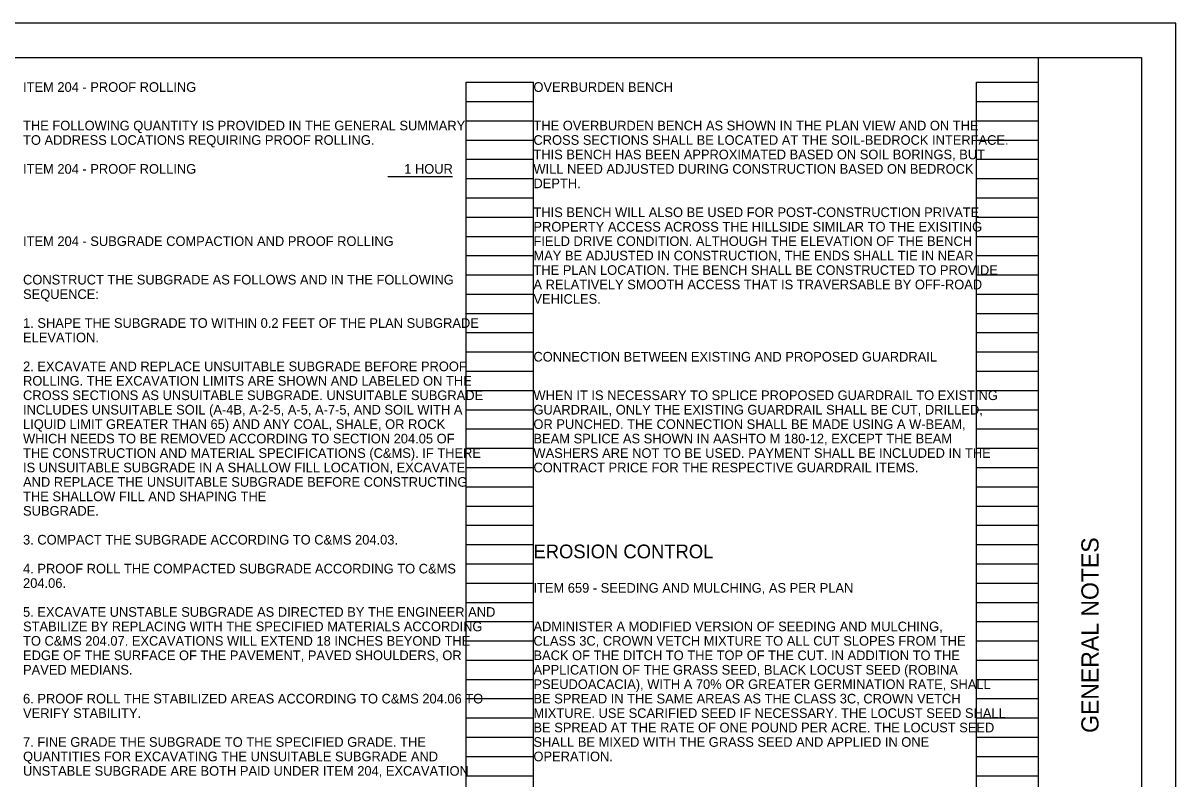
# Model space of a CAD drawing. Extents: x 0 to 34, y 0 to 22.
# Drawn here: x 17.24 to 34, y 11.01 to 22 of the extents above; entities that cross this region are included whole.
import ezdxf

# ---------------------------------------------------------------- set-up
doc = ezdxf.new("R2010")
doc.units = 0
for name, color, linetype in [('SH_Border', 7, 'Continuous'), ('SH_Cut_Line', 7, 'Continuous'), ('SH_Data', 7, 'Continuous'), ('SH_Text', 7, 'Continuous'), ('TX_P_Misc', 7, 'Continuous')]:
    doc.layers.add(name, color=color, linetype=linetype)

msp = doc.modelspace()

# ---------------------------------------------------------------- linework, layer by layer
at = {"layer": 'SH_Border'}
msp.add_line((32, 0.5), (32, 21.5), dxfattribs=at)
msp.add_lwpolyline([(1.5, 21.5), (33.5, 21.5), (33.5, 0.5), (1.5, 0.5)], close=True, dxfattribs=at)
at = {"layer": 'SH_Cut_Line'}
msp.add_lwpolyline([(0, 0), (34, 0), (34, 22), (0, 22)], close=True, dxfattribs=at)
at = {"layer": 'SH_Data'}
for p, q in [((23.68, 0.98), (23.68, 21.14)), ((23.68, 21.14), (24.66, 21.14)), ((24.66, 0.98), (24.66, 21.14)), ((31.1, 0.98), (31.1, 21.14)), ((31.1, 21.14), (32, 21.14)), ((32, 0.98), (32, 21.14)), ((23.68, 20.86), (24.66, 20.86)), ((31.1, 20.86), (32, 20.86)), ((23.68, 20.58), (24.66, 20.58)), ((31.1, 20.58), (32, 20.58)), ((23.68, 20.3), (24.66, 20.3)), ((31.1, 20.3), (32, 20.3)), ((23.68, 20.02), (24.66, 20.02)), ((31.1, 20.02), (32, 20.02)), ((23.68, 19.74), (24.66, 19.74)), ((31.1, 19.74), (32, 19.74)), ((23.68, 19.46), (24.66, 19.46)), ((31.1, 19.46), (32, 19.46)), ((23.68, 19.18), (24.66, 19.18)), ((31.1, 19.18), (32, 19.18)), ((23.68, 18.9), (24.66, 18.9)), ((31.1, 18.9), (32, 18.9)), ((23.68, 18.62), (24.66, 18.62)), ((31.1, 18.62), (32, 18.62)), ((23.68, 18.34), (24.66, 18.34)), ((31.1, 18.34), (32, 18.34)), ((23.68, 18.06), (24.66, 18.06)), ((31.1, 18.06), (32, 18.06)), ((23.68, 17.78), (24.66, 17.78)), ((31.1, 17.78), (32, 17.78)), ((23.68, 17.5), (24.66, 17.5)), ((31.1, 17.5), (32, 17.5)), ((23.68, 17.22), (24.66, 17.22)), ((31.1, 17.22), (32, 17.22)), ((23.68, 16.94), (24.66, 16.94)), ((31.1, 16.94), (32, 16.94)), ((23.68, 16.66), (24.66, 16.66)), ((31.1, 16.66), (32, 16.66)), ((23.68, 16.38), (24.66, 16.38)), ((31.1, 16.38), (32, 16.38)), ((23.68, 16.1), (24.66, 16.1)), ((31.1, 16.1), (32, 16.1)), ((23.68, 15.82), (24.66, 15.82)), ((31.1, 15.82), (32, 15.82)), ((23.68, 15.54), (24.66, 15.54)), ((31.1, 15.54), (32, 15.54)), ((23.68, 15.26), (24.66, 15.26)), ((31.1, 15.26), (32, 15.26)), ((23.68, 14.98), (24.66, 14.98)), ((31.1, 14.98), (32, 14.98)), ((23.68, 14.7), (24.66, 14.7)), ((31.1, 14.7), (32, 14.7)), ((23.68, 14.42), (24.66, 14.42)), ((31.1, 14.42), (32, 14.42)), ((23.68, 14.14), (24.66, 14.14)), ((31.1, 14.14), (32, 14.14)), ((23.68, 13.86), (24.66, 13.86)), ((31.1, 13.86), (32, 13.86)), ((23.68, 13.58), (24.66, 13.58)), ((31.1, 13.58), (32, 13.58)), ((23.68, 13.3), (24.66, 13.3)), ((31.1, 13.3), (32, 13.3)), ((23.68, 13.02), (24.66, 13.02)), ((31.1, 13.02), (32, 13.02)), ((23.68, 12.74), (24.66, 12.74)), ((31.1, 12.74), (32, 12.74)), ((23.68, 12.46), (24.66, 12.46)), ((31.1, 12.46), (32, 12.46)), ((23.68, 12.18), (24.66, 12.18)), ((31.1, 12.18), (32, 12.18)), ((23.68, 11.9), (24.66, 11.9)), ((31.1, 11.9), (32, 11.9)), ((23.68, 11.62), (24.66, 11.62)), ((31.1, 11.62), (32, 11.62)), ((23.68, 11.34), (24.66, 11.34)), ((31.1, 11.34), (32, 11.34)), ((23.68, 11.06), (24.66, 11.06)), ((31.1, 11.06), (32, 11.06))]:
    msp.add_line(p, q, dxfattribs=at)
at = {"layer": 'TX_P_Misc'}
msp.add_line((22.545, 19.771), (23.481, 19.771), dxfattribs=at)

# ---------------------------------------------------------------- texts
at = {"layer": 'SH_Data'}
msp.add_text('GENERAL NOTES', height=0.25, rotation=90, dxfattribs=at).set_placement((32.875, 11.682))
at = {"layer": 'SH_Text'}
for s, height, p in [('ITEM 204 - PROOF ROLLING', 0.14, (17.24, 21)), ('OVERBURDEN BENCH', 0.14, (24.66, 21)), ('THE FOLLOWING QUANTITY IS PROVIDED IN THE GENERAL SUMMARY ', 0.14, (17.24, 20.44)), ('THE OVERBURDEN BENCH AS SHOWN IN THE PLAN VIEW AND ON THE ', 0.14, (24.66, 20.44)), ('TO ADDRESS LOCATIONS REQUIRING PROOF ROLLING.', 0.14, (17.24, 20.23)), ('CROSS SECTIONS SHALL BE LOCATED AT THE SOIL-BEDROCK INTERFACE. ', 0.14, (24.66, 20.23)), ('THIS BENCH HAS BEEN APPROXIMATED BASED ON SOIL BORINGS, BUT ', 0.14, (24.66, 20.02)), ('ITEM 204 - PROOF ROLLING', 0.14, (17.24, 19.81)), ('WILL NEED ADJUSTED DURING CONSTRUCTION BASED ON BEDROCK ', 0.14, (24.66, 19.81)), ('DEPTH.', 0.14, (24.66, 19.6)), ('THIS BENCH WILL ALSO BE USED FOR POST-CONSTRUCTION PRIVATE ', 0.14, (24.66, 19.18)), ('PROPERTY ACCESS ACROSS THE HILLSIDE SIMILAR TO THE EXISITING ', 0.14, (24.66, 18.97)), ('ITEM 204 - SUBGRADE COMPACTION AND PROOF ROLLING', 0.14, (17.24, 18.76)), ('FIELD DRIVE CONDITION. ALTHOUGH THE ELEVATION OF THE BENCH ', 0.14, (24.66, 18.76)), ('MAY BE ADJUSTED IN CONSTRUCTION, THE ENDS SHALL TIE IN NEAR ', 0.14, (24.66, 18.55)), ('THE PLAN LOCATION. THE BENCH SHALL BE CONSTRUCTED TO PROVIDE ', 0.14, (24.66, 18.34)), ('CONSTRUCT THE SUBGRADE AS FOLLOWS AND IN THE FOLLOWING ', 0.14, (17.24, 18.2)), ('A RELATIVELY SMOOTH ACCESS THAT IS TRAVERSABLE BY OFF-ROAD ', 0.14, (24.66, 18.13)), ('SEQUENCE:', 0.14, (17.24, 17.99)), ('VEHICLES.', 0.14, (24.66, 17.92)), ('1. SHAPE THE SUBGRADE TO WITHIN 0.2 FEET OF THE PLAN SUBGRADE ', 0.14, (17.24, 17.57)), ('ELEVATION.', 0.14, (17.24, 17.36)), ('CONNECTION BETWEEN EXISTING AND PROPOSED GUARDRAIL', 0.14, (24.66, 17.08)), ('2. EXCAVATE AND REPLACE UNSUITABLE SUBGRADE BEFORE PROOF ', 0.14, (17.24, 16.94)), ('ROLLING. THE EXCAVATION LIMITS ARE SHOWN AND LABELED ON THE ', 0.14, (17.24, 16.73)), ('CROSS SECTIONS AS UNSUITABLE SUBGRADE. UNSUITABLE SUBGRADE ', 0.14, (17.24, 16.52)), ('WHEN IT IS NECESSARY TO SPLICE PROPOSED GUARDRAIL TO EXISTING ', 0.14, (24.66, 16.52)), ('INCLUDES UNSUITABLE SOIL (A-4B, A-2-5, A-5, A-7-5, AND SOIL WITH A ', 0.14, (17.24, 16.31)), ('GUARDRAIL, ONLY THE EXISTING GUARDRAIL SHALL BE CUT, DRILLED, ', 0.14, (24.66, 16.31)), ('LIQUID LIMIT GREATER THAN 65) AND ANY COAL, SHALE, OR ROCK ', 0.14, (17.24, 16.1)), ('OR PUNCHED. THE CONNECTION SHALL BE MADE USING A W-BEAM, ', 0.14, (24.66, 16.1)), ('WHICH NEEDS TO BE REMOVED ACCORDING TO SECTION 204.05 OF ', 0.14, (17.24, 15.89)), ('BEAM SPLICE AS SHOWN IN AASHTO M 180-12, EXCEPT THE BEAM ', 0.14, (24.66, 15.89)), ('THE CONSTRUCTION AND MATERIAL SPECIFICATIONS (C&MS). IF THERE ', 0.14, (17.24, 15.68)), ('WASHERS ARE NOT TO BE USED. PAYMENT SHALL BE INCLUDED IN THE ', 0.14, (24.66, 15.68)), ('IS UNSUITABLE SUBGRADE IN A SHALLOW FILL LOCATION, EXCAVATE ', 0.14, (17.24, 15.47)), ('CONTRACT PRICE FOR THE RESPECTIVE GUARDRAIL ITEMS.', 0.14, (24.66, 15.47)), ('AND REPLACE THE UNSUITABLE SUBGRADE BEFORE CONSTRUCTING ', 0.14, (17.24, 15.26)), ('THE SHALLOW FILL AND SHAPING THE ', 0.14, (17.24, 15.05)), ('SUBGRADE. ', 0.14, (17.24, 14.84)), ('3. COMPACT THE SUBGRADE ACCORDING TO C&MS 204.03.', 0.14, (17.24, 14.42)), ('EROSION CONTROL', 0.2, (24.66, 14.22)), ('4. PROOF ROLL THE COMPACTED SUBGRADE ACCORDING TO C&MS ', 0.14, (17.24, 14)), ('204.06. ', 0.14, (17.24, 13.79)), ('ITEM 659 - SEEDING AND MULCHING, AS PER PLAN', 0.14, (24.66, 13.72)), ('5. EXCAVATE UNSTABLE SUBGRADE AS DIRECTED BY THE ENGINEER AND ', 0.14, (17.24, 13.37)), ('STABILIZE BY REPLACING WITH THE SPECIFIED MATERIALS ACCORDING ', 0.14, (17.24, 13.16)), ('ADMINISTER A MODIFIED VERSION OF SEEDING AND MULCHING, ', 0.14, (24.66, 13.16)), ('TO C&MS 204.07. EXCAVATIONS WILL EXTEND 18 INCHES BEYOND THE ', 0.14, (17.24, 12.95)), ('CLASS 3C, CROWN VETCH MIXTURE TO ALL CUT SLOPES FROM THE ', 0.14, (24.66, 12.95)), ('EDGE OF THE SURFACE OF THE PAVEMENT, PAVED SHOULDERS, OR ', 0.14, (17.24, 12.74)), ('BACK OF THE DITCH TO THE TOP OF THE CUT. IN ADDITION TO THE ', 0.14, (24.66, 12.74)), ('PAVED MEDIANS. ', 0.14, (17.24, 12.53)), ('APPLICATION OF THE GRASS SEED, BLACK LOCUST SEED (ROBINA ', 0.14, (24.66, 12.53)), ('PSEUDOACACIA), WITH A 70% OR GREATER GERMINATION RATE, SHALL ', 0.14, (24.66, 12.32)), ('6. PROOF ROLL THE STABILIZED AREAS ACCORDING TO C&MS 204.06 TO ', 0.14, (17.24, 12.11)), ('BE SPREAD IN THE SAME AREAS AS THE CLASS 3C, CROWN VETCH ', 0.14, (24.66, 12.11)), ('VERIFY STABILITY. ', 0.14, (17.24, 11.9)), ('MIXTURE. USE SCARIFIED SEED IF NECESSARY. THE LOCUST SEED SHALL ', 0.14, (24.66, 11.9)), ('BE SPREAD AT THE RATE OF ONE POUND PER ACRE. THE LOCUST SEED ', 0.14, (24.66, 11.69)), ('7. FINE GRADE THE SUBGRADE TO THE SPECIFIED GRADE. THE ', 0.14, (17.24, 11.48)), ('SHALL BE MIXED WITH THE GRASS SEED AND APPLIED IN ONE ', 0.14, (24.66, 11.48)), ('QUANTITIES FOR EXCAVATING THE UNSUITABLE SUBGRADE AND ', 0.14, (17.24, 11.27)), ('OPERATION.', 0.14, (24.66, 11.27)), ('UNSTABLE SUBGRADE ARE BOTH PAID UNDER ITEM 204, EXCAVATION ', 0.14, (17.24, 11.06))]:
    msp.add_text(s, height=height, dxfattribs=at).set_placement(p)
at = {"layer": 'TX_P_Misc'}
msp.add_text('1 HOUR', height=0.14, dxfattribs=at).set_placement((22.781, 19.81))

doc.saveas('drawing.dxf')
